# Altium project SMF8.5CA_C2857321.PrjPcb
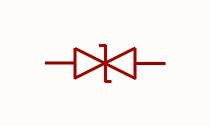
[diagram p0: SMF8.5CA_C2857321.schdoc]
1 sheet, 1 parts. Net scope: global (net labels, ports and power ports of the same name join across sheets).

## Sheet SMF8.5CA_C2857321.schdoc
size 127 x 101 mm

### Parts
D?  smf8.5ca_c2857321  [SOD-123FL_L2.8-W1.8-LS3.7-BI]  (value not drawn)

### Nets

Not connected (* = marked no-connect by the designer): D? 1 2

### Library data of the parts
D? = smf8.5ca_c2857321: 极性:双向;反向截止电压(Vrwm):8.5V;钳位电压:14.4V;峰值脉冲电流(Ipp):13.9A;峰值脉冲功率(Ppp):200W@10/1000us;击穿电压(VBR):9.44V;; Manufacturer: JSMSEMI(杰盛微); AddInBom: yes; ModelId: d105299b3871451c86f679efef28ff8f; ModelTransform: 145.669,70.866,0,0,0,0,0,0,0; Polarity: 双向; Reverse Stand-Off Voltage (Vrwm): 8.5V; Clamping Voltage: 14.4V; Peak Pulse Current (Ipp): 13.9A; Voltage - Breakdown: 9.44V; Reverse Leakage Current (Ir): 10uA; Number of Channels: 单路; Type: TVS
